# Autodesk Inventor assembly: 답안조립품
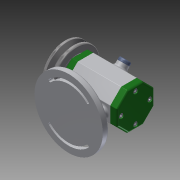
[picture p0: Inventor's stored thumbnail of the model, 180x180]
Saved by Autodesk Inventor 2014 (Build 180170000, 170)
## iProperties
Created: 2017-06
Part Number: 답안조립품
Document SubType Name: Assembly
Designer: net
Author: net
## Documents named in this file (14)
- C:\Users\net\Desktop\470607V1014\답안조립품.iam
- C:\Users\net\Desktop\470607V1014\본체.ipt
- C:\Users\net\Desktop\470607V1014\축.ipt
- C:\Users\net\Desktop\470607V1014\키 3 x 3 x 12.ipt
- C:\Users\net\Desktop\470607V1014\V벨트풀리.ipt
- C:\Users\net\Desktop\470607V1014\와셔 8x17.ipt
- C:\Users\net\Desktop\470607V1014\스프링와셔 8.ipt
- C:\Users\net\Desktop\470607V1014\너트 M 8.ipt
- C:\Users\net\Desktop\470607V1014\앞커버.ipt
- C:\Users\net\Desktop\470607V1014\볼트 M4 x 12.ipt
- C:\Users\net\Desktop\470607V1014\베어링 15 x 32 x 9.ipt
- C:\Users\net\Desktop\470607V1014\뒤커버.ipt
- C:\Users\net\Desktop\470607V1014\오일 실 15 25 7.ipt
- C:\Users\net\Desktop\470607V1014\고무캡.ipt
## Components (2 placed, 2 different names)
1. V벨트풀리:1
2. 고무캡:1
